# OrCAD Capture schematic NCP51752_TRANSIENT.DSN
size B; title: NCP51752; rev: 0
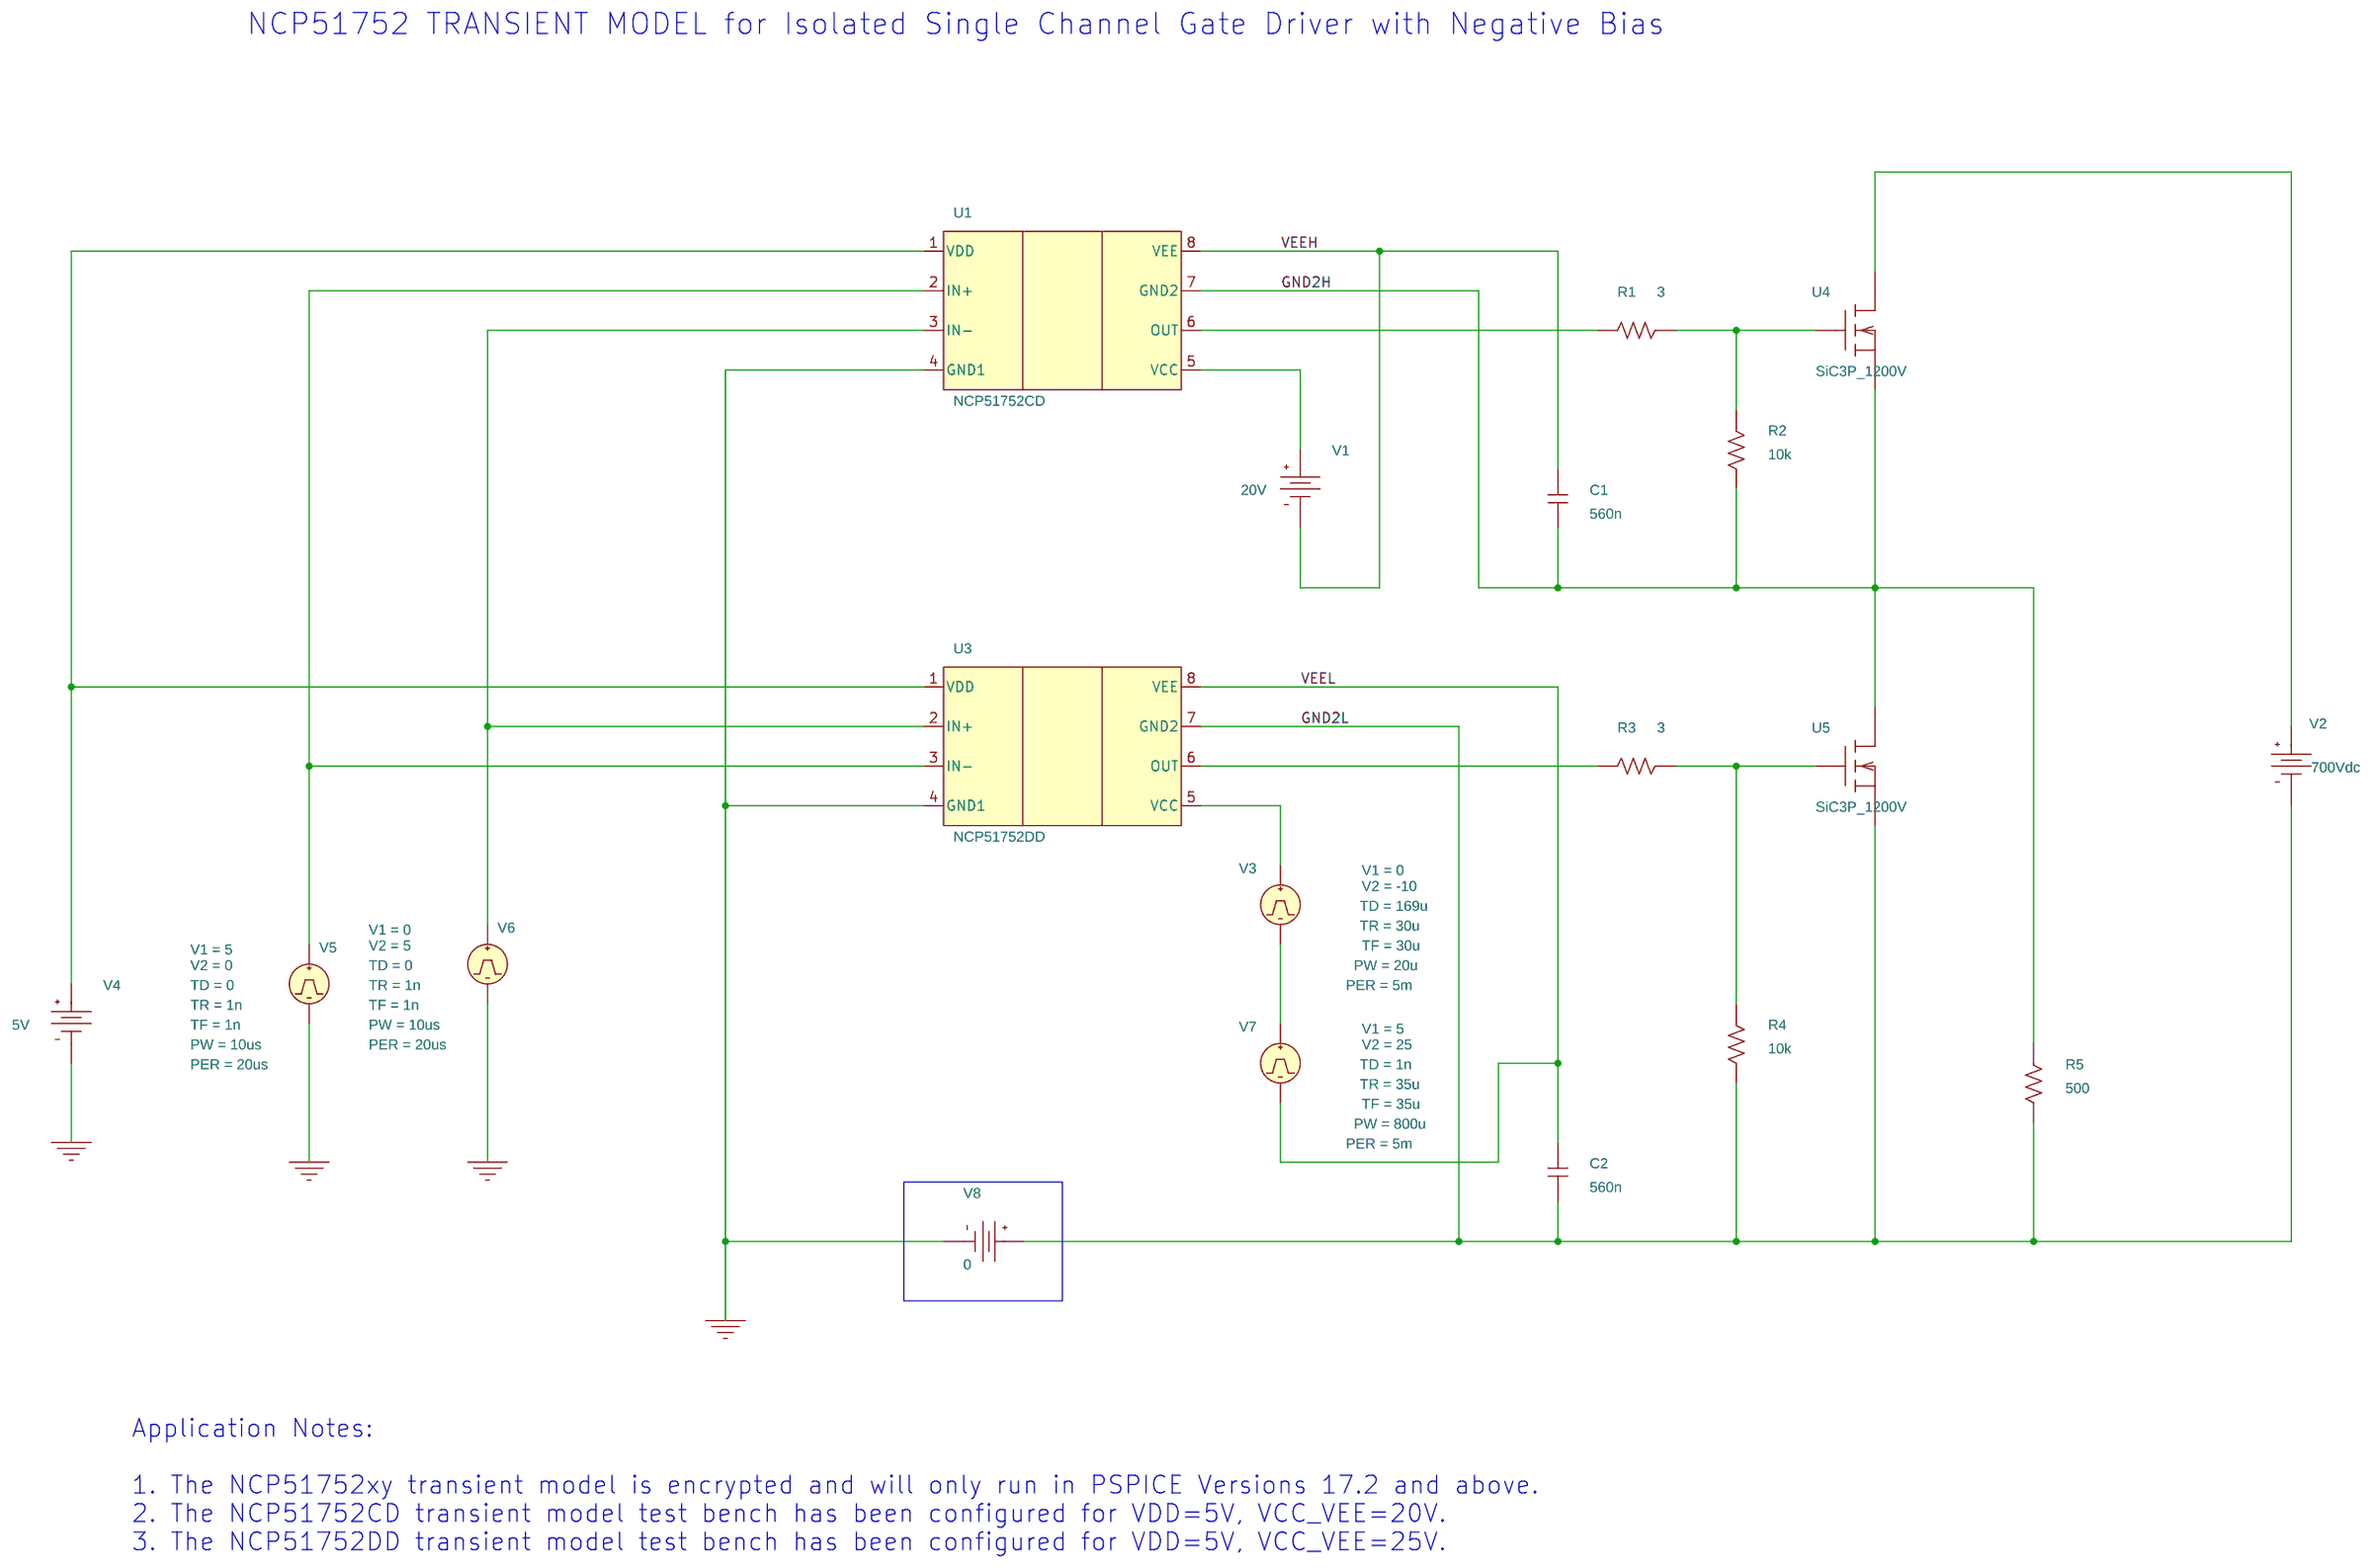
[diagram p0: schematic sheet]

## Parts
C1  560n  [RAD/CK05]
C2  560n  [RAD/CK05]
R1  3  [AX/RC05]
R2  10k  [AX/RC05]
R3  3  [AX/RC05]
R4  10k  [AX/RC05]
R5  500  [AX/RC05]
U1  NCP51752CD
U3  NCP51752DD
U4  SiC3P_1200V
U5  SiC3P_1200V
V1  VDC
V2  VDC
V3  VPULSE
V4  VDC
V5  VPULSE
V6  VPULSE
V7  VPULSE
V8  VDC

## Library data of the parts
C1 C2 = C: IC: 0
R1-R5 = R
U1 = NCP51752CD
U3 = NCP51752DD
U4 U5 = SICMOSFET_3P
V1 = VDC: DC: 20V
V2 = VDC: DC: 700Vdc
V3 = VPULSE: PER: 5m; PW: 20u; TD: 169u; TF: 30u; TR: 30u; V1: 0; V2: -10
V4 = VDC: DC: 5V
V5 = VPULSE: PER: 20us; PW: 10us; TD: 0; TF: 1n; TR: 1n; V1: 5; V2: 0
V6 = VPULSE: PER: 20us; PW: 10us; TD: 0; TF: 1n; TR: 1n; V1: 0; V2: 5
V7 = VPULSE: PER: 5m; PW: 800u; TD: 1n; TF: 35u; TR: 35u; V1: 5; V2: 25
V8 = VDC: DC: 0

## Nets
GND2H: C1.2 R2.2 R5.1 U1.7(GND2) U4.3(S) U5.1(D)
GND2L: C2.2 R4.2 R5.2 U3.7(GND2) U5.3(S) V2.1(-) V8.0(+)
VEEH: C1.1 U1.8(VEE) V1.1(-)
VEEL: C2.1 U3.8(VEE) V7.2(-)
0: U1.4(GND1) U3.4(GND1) V4.1(-) V5.2(-) V6.2(-) V8.1(-)
N16958254: R3.1 R4.1 U5.2(G)
N17012757: U3.5(VCC) V3.1(+)
N17012769: R3.2 U3.6(OUT)
N17012960: U1.1(VDD) U3.1(VDD) V4.0(+)
N17012965: U1.2(IN+) U3.3(IN-) V5.1(+)
N17013085: R1.1 R2.1 U4.2(G)
N17013201: U4.1(D) V2.0(+)
N17013284: U1.5(VCC) V1.0(+)
N17013372: U1.3(IN-) U3.2(IN+) V6.1(+)
N17014578: R1.2 U1.6(OUT)
N17049784: V3.2(-) V7.1(+)

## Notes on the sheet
- NCP51752 TRANSIENT MODEL for Isolated Single Channel Gate Driver with Negative Bias
- Application Notes:
  1. The NCP51752xy transient model is encrypted and will only run in PSPICE Versions 17.2 and above.
  2. The NCP51752CD transient model test bench has been configured for VDD=5V, VCC_VEE=20V.
  3. The NCP51752DD transient model test bench has been configured for VDD=5V, VCC_VEE=25V.
